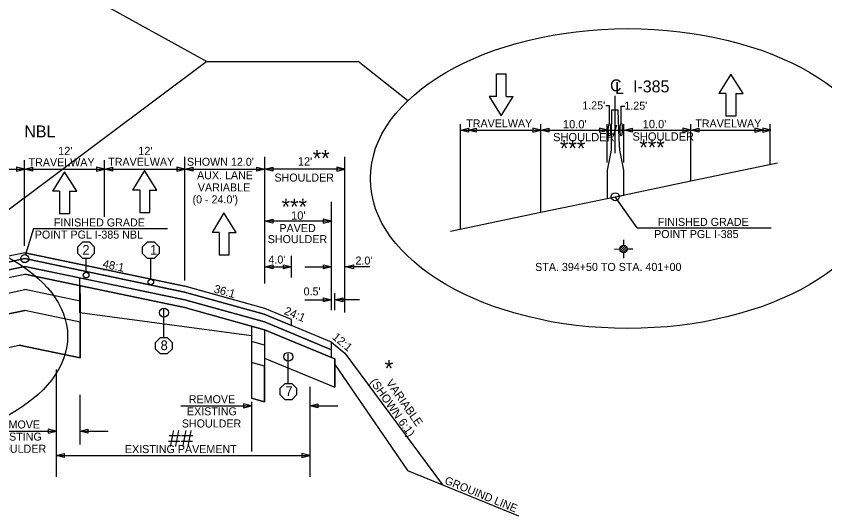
# Model space of a CAD drawing. Extents: x 4832 to 5477, y 4935 to 5220.
# Drawn here: x 5211.3 to 5332.6, y 5056.7 to 5131.6 of the extents above; entities that cross this region are included whole.
import ezdxf

# ---------------------------------------------------------------- set-up
doc = ezdxf.new("R2010")
doc.units = 0
for name, color, linetype in [('Level 3', 7, 'Continuous'), ('RD_EX_SU_Pole', 7, 'Continuous'), ('RD_QTY_Intermediate', 7, 'Continuous'), ('RD_QTY_Sub_Base', 7, 'Continuous'), ('RD_QTY_Surf_Course', 7, 'Continuous'), ('RD_SHT_Typical', 7, 'Continuous'), ('RD_TX_Misc1', 7, 'Continuous'), ('RD_TX_TypSect', 7, 'Continuous'), ('RD_XS_ExGround', 7, 'Continuous'), ('RD_XS_ExPaveRet', 7, 'Continuous'), ('TERMINATOR', 7, 'Continuous'), ('title', 7, 'Continuous'), ('typical1', 7, 'Continuous'), ('typical_on', 7, 'Continuous')]:
    doc.layers.add(name, color=color, linetype=linetype)

# ---------------------------------------------------------------- blocks, each defined once
blk = doc.blocks.new('AH')
at = {"layer": 'TERMINATOR'}
blk.add_lwpolyline([(-6, 1.5), (0, 0), (-6, -1.5)], close=True, dxfattribs=at)
blk = doc.blocks.new('SUE_TFP')
at = {"layer": 'RD_EX_SU_Pole'}
for p, q in [((0, 5.5), (0, 2.22)), ((-2.21, 0.13), (-0.13, 2.21)), ((-1.96, -1.03), (1.03, 1.96)), ((-1.31, -1.79), (1.79, 1.31)), ((-0.3, -2.2), (2.2, 0.3)), ((2.22, 0), (5.53, 0.01)), ((-5.53, -0.01), (-2.22, 0)), ((0, -2.22), (0, -5.5))]:
    blk.add_line(p, q, dxfattribs=at)
blk.add_circle((0, 0), 2.22, dxfattribs=at)

msp = doc.modelspace()

# ---------------------------------------------------------------- linework, layer by layer
at = {"layer": 'RD_QTY_Intermediate'}
for p, q in [((5212.59, 5094.09), (5200.58, 5091.58)), ((5200.58, 5090.42), (5212.59, 5092.92)), ((5236.59, 5089.08), (5212.59, 5094.09)), ((5212.59, 5092.92), (5236.59, 5087.92))]:
    msp.add_line(p, q, dxfattribs=at)
msp.add_lwpolyline([(5236.59, 5087.92), (5248.57, 5084.59), (5258.59, 5080.42), (5258.59, 5081.58), (5248.57, 5085.76), (5236.59, 5089.08)], dxfattribs=at)
at = {"layer": 'RD_QTY_Sub_Base'}
for p, q in [((5212.59, 5087.46), (5200.58, 5084.96)), ((5220.89, 5085.73), (5212.59, 5087.46)), ((5220.89, 5080.37), (5220.89, 5085.73)), ((5200.67, 5079.97), (5211.76, 5082.28)), ((5211.76, 5082.28), (5220.89, 5080.37))]:
    msp.add_line(p, q, dxfattribs=at)
at = {"layer": 'RD_QTY_Surf_Course'}
for p, q in [((5212.59, 5095.25), (5200.58, 5092.74)), ((5220.88, 5093.52), (5212.59, 5095.25)), ((5200.58, 5091.58), (5212.59, 5094.09)), ((5236.58, 5090.24), (5220.88, 5093.52))]:
    msp.add_line(p, q, dxfattribs=at)
for points in [[(5212.59, 5094.09), (5220.86, 5092.36), (5220.87, 5092.36)], [(5220.87, 5092.36), (5220.88, 5092.36), (5236.59, 5089.08), (5248.57, 5085.76), (5258.59, 5081.58), (5258.59, 5082.74), (5248.48, 5086.94), (5236.58, 5090.24)]]:
    msp.add_lwpolyline(points, dxfattribs=at)
at = {"layer": 'RD_SHT_Typical'}
for p, q in [((5212.59, 5096.13), (5200.58, 5093.63)), ((5212.59, 5096.13), (5200.58, 5093.63)), ((5212.59, 5096.13), (5236.6, 5091.13)), ((5200.58, 5092.74), (5212.59, 5095.25)), ((5200.58, 5092.74), (5212.59, 5095.25)), ((5220.88, 5093.52), (5212.59, 5095.25)), ((5212.59, 5095.25), (5220.88, 5093.52)), ((5200.58, 5091.58), (5212.59, 5094.09)), ((5200.58, 5090.42), (5212.59, 5092.92)), ((5236.59, 5089.08), (5212.59, 5094.09)), ((5236.59, 5087.92), (5212.59, 5092.92)), ((5236.6, 5090.24), (5220.88, 5093.52)), ((5200.58, 5088.1), (5212.59, 5090.6)), ((5220.89, 5088.87), (5212.59, 5090.6)), ((5220.88, 5091.2), (5220.89, 5088.87)), ((5248.58, 5087.8), (5236.58, 5091.13)), ((5236.58, 5090.24), (5248.48, 5086.94)), ((5220.89, 5088.87), (5220.89, 5085.73)), ((5248.57, 5085.76), (5236.57, 5089.09)), ((5200.58, 5084.96), (5212.59, 5087.46)), ((5220.89, 5085.73), (5212.59, 5087.46)), ((5248.57, 5084.59), (5236.57, 5087.93)), ((5248.48, 5086.95), (5252.58, 5085.24)), ((5248.48, 5086.95), (5252.58, 5085.24)), ((5252.58, 5086.13), (5248.58, 5087.8)), ((5252.58, 5086.13), (5248.58, 5087.8)), ((5220.89, 5085.73), (5220.89, 5080.37)), ((5248.57, 5085.76), (5258.59, 5081.58)), ((5252.58, 5085.24), (5252.58, 5086.13)), ((5252.58, 5085.24), (5252.58, 5086.13)), ((5246.61, 5085.14), (5246.61, 5074.32)), ((5248.57, 5084.59), (5248.57, 5073.77)), ((5248.57, 5084.59), (5259.09, 5080.21)), ((5258.59, 5082.74), (5252.58, 5085.24)), ((5258.59, 5082.74), (5252.58, 5085.24)), ((5200.67, 5079.97), (5211.76, 5082.28)), ((5220.89, 5080.37), (5211.76, 5082.28)), ((5248.57, 5082.28), (5246.61, 5082.82)), ((5258.59, 5081.58), (5258.59, 5082.74)), ((5258.59, 5082.74), (5260.58, 5081.07)), ((5258.59, 5080.42), (5258.59, 5081.58)), ((5260.58, 5081.07), (5275.27, 5061.33)), ((5248.57, 5079.14), (5246.61, 5079.68)), ((5248.57, 5080.35), (5259.09, 5075.97)), ((5259.09, 5080.21), (5259.09, 5075.97)), ((5248.57, 5073.77), (5246.61, 5074.32))]:
    msp.add_line(p, q, dxfattribs=at)
for points in [[(5236.58, 5091.13), (5224.6, 5093.63), (5212.59, 5096.13)], [(5220.88, 5093.52), (5236.58, 5090.24), (5236.6, 5090.24)], [(5248.58, 5087.8), (5236.6, 5091.13), (5236.58, 5091.13)], [(5236.58, 5091.13), (5236.58, 5091.13)], [(5236.6, 5090.24), (5236.6, 5090.24)], [(5236.6, 5090.24), (5246.61, 5087.47), (5247.16, 5087.32), (5248.48, 5086.95)]]:
    msp.add_lwpolyline(points, dxfattribs=at)
at = {"layer": 'RD_TX_Misc1'}
for p, q in [((5283.34, 5122.98), (5284.8, 5122.99)), ((5283.34, 5119.58), (5283.34, 5122.98)), ((5284.8, 5119.59), (5284.8, 5122.99)), ((5318.5, 5122.93), (5316.72, 5120)), ((5320.33, 5120.01), (5318.5, 5122.93)), ((5283.34, 5119.58), (5282.25, 5119.58)), ((5282.25, 5119.58), (5284.07, 5116.66)), ((5284.07, 5116.66), (5285.86, 5119.59)), ((5284.8, 5119.59), (5285.86, 5119.59)), ((5317.77, 5120), (5316.72, 5120)), ((5317.77, 5120), (5317.77, 5116.6)), ((5319.23, 5120.01), (5320.33, 5120.01)), ((5319.23, 5120.01), (5319.23, 5116.6)), ((5319.23, 5116.6), (5317.77, 5116.6)), ((5218.56, 5108.28), (5216.78, 5105.35)), ((5220.39, 5105.36), (5218.56, 5108.28)), ((5230.57, 5108.46), (5228.78, 5105.53)), ((5232.39, 5105.54), (5230.57, 5108.46)), ((5217.83, 5105.35), (5216.78, 5105.35)), ((5217.83, 5105.35), (5217.83, 5101.95)), ((5219.29, 5105.36), (5220.39, 5105.36)), ((5219.29, 5105.36), (5219.29, 5101.96)), ((5229.84, 5105.53), (5228.78, 5105.53)), ((5229.84, 5105.53), (5229.84, 5102.13)), ((5231.3, 5105.54), (5232.39, 5105.54)), ((5231.3, 5105.54), (5231.3, 5102.14)), ((5219.29, 5101.96), (5217.83, 5101.95)), ((5231.3, 5102.14), (5229.84, 5102.13)), ((5242.47, 5102.1), (5240.69, 5099.18)), ((5244.3, 5099.19), (5242.47, 5102.1)), ((5241.74, 5099.18), (5240.69, 5099.18)), ((5241.74, 5099.18), (5241.74, 5095.77)), ((5243.2, 5099.19), (5244.3, 5099.19)), ((5243.2, 5099.19), (5243.2, 5095.78)), ((5243.2, 5095.78), (5241.74, 5095.77))]:
    msp.add_line(p, q, dxfattribs=at)
at = {"layer": 'RD_TX_TypSect'}
for p, q in [((5212.87, 5139.76), (5239.92, 5124.84)), ((5239.92, 5124.84), (5204.05, 5098.02)), ((5239.92, 5124.84), (5262.62, 5124.84)), ((5270.04, 5118.93), (5262.62, 5124.84)), ((5301.14, 5111.09), (5301.14, 5119.65)), ((5300.3, 5118.19), (5299.75, 5118.19)), ((5300.3, 5115.55), (5300.3, 5118.19)), ((5300.58, 5117.51), (5300.56, 5113.2)), ((5300.58, 5117.51), (5300.58, 5117.51)), ((5301.09, 5117.51), (5300.58, 5117.51)), ((5301.61, 5117.51), (5301.09, 5117.51)), ((5301.76, 5113.21), (5301.61, 5117.51)), ((5302.07, 5115.55), (5302.07, 5118.13)), ((5302.07, 5118.13), (5302.59, 5118.13)), ((5277.93, 5099.69), (5277.93, 5115.41)), ((5290, 5102.21), (5290, 5115.41)), ((5299.93, 5109.67), (5299.93, 5115.41)), ((5300.9, 5113.71), (5301.38, 5115.32)), ((5302.43, 5109.67), (5302.43, 5115.41)), ((5312.49, 5106.9), (5312.49, 5115.41)), ((5324.4, 5109.38), (5324.4, 5115.41)), ((5277.93, 5114.51), (5290, 5114.51)), ((5290, 5114.51), (5300, 5114.51)), ((5300, 5114.51), (5302.49, 5114.51)), ((5302.49, 5114.51), (5312.49, 5114.51)), ((5312.49, 5114.51), (5324.48, 5114.51)), ((5300.56, 5113.2), (5300.56, 5113.2)), ((5212.58, 5097.15), (5212.58, 5110.04)), ((5224.58, 5101.51), (5224.58, 5110.04)), ((5236.59, 5091.98), (5236.59, 5110.5)), ((5248.6, 5091.53), (5248.6, 5110.5)), ((5260.61, 5087.2), (5260.61, 5110.5)), ((5200.57, 5108.67), (5212.58, 5108.67)), ((5212.58, 5108.67), (5224.58, 5108.67)), ((5224.58, 5108.67), (5236.59, 5108.67)), ((5236.59, 5108.67), (5248.59, 5108.67)), ((5260.59, 5108.67), (5248.59, 5108.67)), ((5312.49, 5106.9), (5325.5, 5109.61)), ((5299.93, 5106.52), (5299.93, 5104.28)), ((5301.17, 5104.54), (5312.49, 5106.9)), ((5290, 5102.21), (5301.17, 5104.54)), ((5299.93, 5104.28), (5301.17, 5104.54)), ((5301.17, 5104.54), (5302.43, 5104.79)), ((5304.46, 5099.85), (5301.17, 5104.54)), ((5258.61, 5087.55), (5258.61, 5103.79)), ((5276.45, 5099.39), (5290, 5102.21)), ((5258.58, 5100.87), (5248.58, 5100.87)), ((5213.89, 5099.77), (5212.71, 5095.86)), ((5213.89, 5099.77), (5234, 5099.77)), ((5304.46, 5099.85), (5324.57, 5099.85)), ((5252.6, 5092.43), (5252.6, 5095.68)), ((5221.8, 5093.2), (5221.8, 5095.28)), ((5231.51, 5092.17), (5231.51, 5095.28)), ((5248.6, 5094.03), (5252.6, 5094.03)), ((5254.59, 5094.03), (5258.58, 5094.03)), ((5264.36, 5094.03), (5260.68, 5094.03)), ((5259.11, 5087.55), (5259.11, 5090.05)), ((5254.61, 5089.06), (5258.61, 5089.06)), ((5262.78, 5089.06), (5259.11, 5089.06)), ((5233.45, 5083.43), (5233.45, 5087.83)), ((5252.12, 5076.55), (5252.12, 5080.96)), ((5217.33, 5078.63), (5217.33, 5062.53)), ((5255.35, 5076.03), (5255.35, 5062.53)), ((5220.88, 5074.84), (5220.88, 5067.4)), ((5246.59, 5073.8), (5246.59, 5066.32)), ((5236, 5073.18), (5246.59, 5073.18)), ((5255.35, 5073.18), (5259.57, 5073.18)), ((5206.75, 5069.39), (5217.33, 5069.39)), ((5220.88, 5069.39), (5225.1, 5069.39)), ((5217.33, 5065.75), (5255.35, 5065.75))]:
    msp.add_line(p, q, dxfattribs=at)
for points in [[(5300.56, 5113.2), (5300.53, 5111.5), (5299.93, 5108.54), (5299.93, 5106.52)], [(5302.43, 5104.79), (5302.43, 5106.51), (5302.43, 5108.54), (5301.83, 5111.5), (5301.76, 5113.21)]]:
    msp.add_lwpolyline(points, dxfattribs=at)
for centre, radius in [((5301.17, 5104.54), 0.6), ((5212.59, 5095.25), 0.6), ((5221.8, 5092.78), 0.42), ((5231.51, 5091.75), 0.42), ((5233.47, 5087.15), 0.667), ((5252.12, 5080.53), 0.667)]:
    msp.add_circle(centre, radius, dxfattribs=at)
for centre, major_axis, ratio in [((5303.06, 5107.27), (38.62, 0), 0.582122), ((5300.29, 5114.59), (0.008, 0.953), 0.172853), ((5302.06, 5114.59), (0.008, 0.953), 0.172853), ((5188.54, 5083.59), (30.49, 0), 0.549804)]:
    msp.add_ellipse(centre, major_axis=major_axis, ratio=ratio, dxfattribs=at)
at = {"layer": 'RD_XS_ExGround'}
msp.add_lwpolyline([(5259.09, 5079.38), (5269.98, 5063.49), (5286.65, 5056.68)], dxfattribs=at)
at = {"layer": 'RD_XS_ExPaveRet'}
for p, q in [((5220.88, 5087.14), (5220.88, 5092.36)), ((5246.61, 5085.14), (5246.61, 5083.68)), ((5248.57, 5079.14), (5246.61, 5079.68)), ((5246.61, 5079.68), (5246.61, 5074.32)), ((5248.57, 5073.77), (5248.57, 5079.14)), ((5246.61, 5074.32), (5248.57, 5073.77))]:
    msp.add_line(p, q, dxfattribs=at)
msp.add_lwpolyline([(5220.87, 5087.14), (5220.86, 5091.2), (5236.59, 5087.92), (5246.61, 5085.14), (5246.59, 5083.68)], close=True, dxfattribs=at)
msp.add_lwpolyline([(5248.57, 5079.14), (5248.57, 5079.14)], dxfattribs=at)
at = {"layer": 'title'}
msp.add_line((5224.34, 5093.63), (5224.84, 5093.63), dxfattribs=at)
at = {"layer": 'typical1'}
for q in [(5248.57, 5080.35), (5259.09, 5075.97)]:
    msp.add_line((5248.57, 5080.35), q, dxfattribs=at)
for points in [[(5259.09, 5080.21), (5258.59, 5080.42), (5248.57, 5084.59)], [(5248.57, 5084.59), (5248.57, 5082.28), (5248.57, 5080.35)], [(5259.09, 5075.97), (5259.09, 5080.21), (5259.09, 5080.21)]]:
    msp.add_lwpolyline(points, dxfattribs=at)
at = {"layer": 'typical_on'}
for points in [[(5223.03, 5097.02), (5223.03, 5096), (5222.31, 5095.28), (5221.29, 5095.28), (5220.57, 5096), (5220.57, 5097.02), (5221.29, 5097.75), (5222.31, 5097.75)], [(5232.74, 5097.02), (5232.74, 5096), (5232.02, 5095.28), (5231, 5095.28), (5230.28, 5096), (5230.28, 5097.02), (5231, 5097.75), (5232.02, 5097.75)], [(5234.69, 5082.7), (5234.69, 5081.68), (5233.97, 5080.96), (5232.95, 5080.96), (5232.23, 5081.68), (5232.23, 5082.7), (5232.95, 5083.42), (5233.97, 5083.42)], [(5253.37, 5075.83), (5253.37, 5074.81), (5252.65, 5074.09), (5251.63, 5074.09), (5250.91, 5074.81), (5250.91, 5075.83), (5251.63, 5076.55), (5252.65, 5076.55)]]:
    msp.add_lwpolyline(points, close=True, dxfattribs=at)

# ---------------------------------------------------------------- block references
at = {"layer": 'Level 3', "xscale": 0.24999999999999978, "yscale": 0.24999999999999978}
msp.add_blockref('SUE_TFP', (5302.41, 5096.7), dxfattribs=at)
at = {"layer": 'RD_QTY_Surf_Course', "xscale": 0.20020004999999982, "yscale": -0.20020004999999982}
for p in [(5212.58, 5108.67), (5224.58, 5108.67), (5236.59, 5108.67), (5260.59, 5108.67), (5258.58, 5100.87), (5246.59, 5073.18), (5217.33, 5069.39), (5255.35, 5065.75)]:
    msp.add_blockref('AH', p, dxfattribs=at)
at = {"layer": 'RD_QTY_Surf_Course', "xscale": 0.20020004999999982, "yscale": 0.20020004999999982, "rotation": 180}
for p in [(5212.58, 5108.67), (5224.58, 5108.67), (5248.59, 5108.67), (5248.58, 5100.87), (5255.35, 5073.18), (5220.88, 5069.39), (5217.33, 5065.75)]:
    msp.add_blockref('AH', p, dxfattribs=at)
at = {"layer": 'TERMINATOR'}
for p, xscale, yscale, rotation in [((5277.93, 5114.51), 0.2000217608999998, 0.2000217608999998, 180), ((5279.12, 5114.51), 0.2000217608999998, 0.2000217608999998, 180), ((5290, 5114.51), 0.2000217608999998, 0.2000217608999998, 180), ((5302.49, 5114.51), 0.2000217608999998, 0.2000217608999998, 180), ((5312.49, 5114.51), 0.2000217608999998, 0.2000217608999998, 180), ((5236.59, 5108.67), 0.20002176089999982, 0.20002176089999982, 179.99858211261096), ((5248.59, 5108.67), 0.20002176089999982, 0.20002176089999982, -0.0014178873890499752), ((5248.6, 5094.03), 0.2000217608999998, 0.2000217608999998, 180), ((5260.68, 5094.03), 0.19992179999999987, 0.19992179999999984, 180), ((5259.11, 5089.06), 0.19992179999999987, 0.19992179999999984, 180)]:
    msp.add_blockref('AH', p, dxfattribs=dict(at, xscale=xscale, yscale=yscale, rotation=rotation))
for p, xscale, yscale in [((5290, 5114.51), 0.2000217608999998, -0.2000217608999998), ((5300, 5114.51), 0.2000217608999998, -0.2000217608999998), ((5312.49, 5114.51), 0.2000217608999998, -0.2000217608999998), ((5323.29, 5114.51), 0.2000217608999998, -0.2000217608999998), ((5324.48, 5114.51), 0.2000217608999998, -0.2000217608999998), ((5252.6, 5094.03), 0.2000217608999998, 0.2000217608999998), ((5258.58, 5094.03), 0.19992179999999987, 0.19992179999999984), ((5258.61, 5089.06), 0.19992179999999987, 0.19992179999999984)]:
    msp.add_blockref('AH', p, dxfattribs=dict(at, xscale=xscale, yscale=yscale))

# ---------------------------------------------------------------- texts
at = {"layer": 'RD_TX_TypSect'}
for s, height, p in [('C', 1.79, (5300.38, 5120.35)), ('I-385', 1.791, (5303.83, 5120.19)), ('L', 1.79, (5301.14, 5119.95)), ("1.25'", 1.2, (5296.22, 5117.64)), ("1.25'", 1.2, (5302.53, 5117.6)), ("10.0'", 1.241, (5293.32, 5114.79)), ("10.0'", 1.241, (5305.28, 5114.82)), ('NBL', 1.791, (5212.53, 5113.44)), ('SHOULDER', 1.241, (5291.84, 5112.86)), ('SHOULDER', 1.241, (5303.75, 5112.95)), ('***', 2.443, (5292.86, 5110.59)), ('***', 2.443, (5304.77, 5110.71)), ("12'", 1.241, (5217.59, 5110.78)), ("12'", 1.241, (5229.6, 5110.78)), ('**', 2.443, (5255.79, 5109.1)), ("12'", 1.241, (5253.55, 5109.21)), ('SHOULDER', 1.2, (5250.05, 5106.81)), ('VARIABLE', 1.2, (5238.56, 5105.34)), ("(0 - 24.0')", 1.2, (5237.76, 5103.54)), ('***', 2.443, (5251.12, 5101.82)), ("10'", 1.241, (5252.54, 5101.1)), ('FINISHED GRADE', 1.2001, (5216.97, 5100.08)), ('PAVED', 1.2, (5250.8, 5099.24)), ('FINISHED GRADE', 1.2001, (5307.54, 5100.16)), ('POINT PGL I-385 NBL', 1.2001, (5214.1, 5098.26)), ('POINT PGL I-385', 1.2001, (5306.99, 5098.34)), ('SHOULDER', 1.2, (5249.04, 5097.58)), ('2', 1.45, (5221.24, 5095.85)), ('1', 1.45, (5231.39, 5095.85)), ('STA. 394+50 TO STA. 401+00', 1.2, (5289.15, 5093.41)), ('8', 1.45, (5232.97, 5081.53)), ('*', 2.5, (5266.56, 5077.55)), ('7', 1.45, (5251.7, 5074.66)), ('##', 2.5, (5234.14, 5067.04)), ('EXISTING PAVEMENT', 1.2001, (5227.62, 5066.09))]:
    msp.add_text(s, height=height, dxfattribs=at).set_placement(p)
for s, height, rotation, p in [('TRAVELWAY', 1.2, 359.9986, (5278.81, 5114.94)), ('TRAVELWAY', 1.2, 359.9986, (5313.17, 5114.93)), ('TRAVELWAY', 1.2, 359.9986, (5213.17, 5109.11)), ('TRAVELWAY', 1.2, 359.9986, (5225.11, 5109.18)), ("SHOWN 12.0'", 1.2, 359.9993, (5236.92, 5109.18)), ('AUX. LANE', 1.2, 0.0014, (5238.44, 5107.17)), ("4.0'", 1.2, 0.0014, (5249.15, 5094.52)), ("2.0'", 1.2, 0.0014, (5262.2, 5094.37)), ('48:1', 1.241, 348.324, (5224.22, 5093.92)), ('36:1', 1.241, 344.4759, (5240.86, 5090.19)), ("0.5'", 1.2, 0.0014, (5254.42, 5089.74)), ('24:1', 1.241, 337.382, (5251.39, 5086.96)), ('12:1', 1.241, 320.1967, (5258.61, 5083.31)), ('(SHOWN 6:1)', 1.2407, 305.0807, (5264.32, 5076.78)), ('VARIABLE', 1.241, 305.0807, (5266.71, 5076.62)), ('REMOVE', 1.2, 360, (5237.2, 5073.57)), ('EXISTING', 1.2, 360, (5236.92, 5071.75)), ('SHOULDER', 1.2, 360, (5236.15, 5069.93)), ('REMOVE', 1.2, 360, (5207.94, 5069.78)), ('EXISTING', 1.2, 360, (5207.66, 5067.96)), ('SHOULDER', 1.2, 360, (5206.89, 5066.14)), ('GROUIND LINE', 1.2, 337.7669, (5275.46, 5061.54))]:
    msp.add_text(s, height=height, rotation=rotation, dxfattribs=at).set_placement(p)

doc.saveas('drawing.dxf')
